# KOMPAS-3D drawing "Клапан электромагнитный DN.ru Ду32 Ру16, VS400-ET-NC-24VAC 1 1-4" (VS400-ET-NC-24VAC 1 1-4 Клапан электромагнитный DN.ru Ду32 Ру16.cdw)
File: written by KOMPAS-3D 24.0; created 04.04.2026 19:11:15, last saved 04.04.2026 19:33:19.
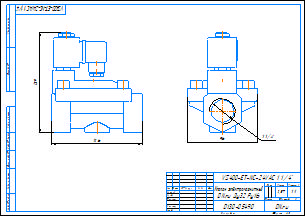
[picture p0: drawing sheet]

Document properties: c3d_UniqueCompID: ef56311e-7521-43dc-8291-0e6108b3d81d; Обозначение: VS400-ET-NC-220VAC 1; Наименование: Клапан электромагнитный DN.ru Ду25 Ру16; Автор: artio; Класс точности: c; Знак неуказанной шероховатости: Шероховатость не задана; Рассекать на разрезах: Да; c3d_UniqueCompID: ef56311e-7521-43dc-8291-0e6108b3d81d; Обозначение: VS400-ET-NC-220VAC 1-2; Наименование: Клапан электромагнитный DN.ru Ду15 Ру16; Автор: artio; Класс точности: c; Знак неуказанной шероховатости: Шероховатость не задана; Рассекать на разрезах: Да; c3d_UniqueCompID: ef56311e-7521-43dc-8291-0e6108b3d81d; Обозначение: VS400-ET-NC-220VAC 3-4; Наименование: Клапан электромагнитный DN.ru Ду20 Ру16; Автор: artio; Класс точности: c; Знак неуказанной шероховатости: Шероховатость не задана; Рассекать на разрезах: Да; c3d_UniqueCompID: ef56311e-7521-43dc-8291-0e6108b3d81d; Обозначение: VS400-ET-NC-220VAC 1 1-4; Наименование: Клапан электромагнитный DN.ru Ду32 Ру16; Автор: artio; Класс точности: c; Знак неуказанной шероховатости: Шероховатость не задана; Рассекать на разрезах: Да; c3d_UniqueCompID: ef56311e-7521-43dc-8291-0e6108b3d81d; Обозначение: VS400-ET-NC-220VAC 3-8; Наименование: Клапан электромагнитный DN.ru Ду10 Ру16; Автор: artio; Класс точности: c; Знак неуказанной шероховатости: Шероховатость не задана; Рассекать на разрезах: Да; Автор: artio; Форматы листов документа: A3; Полное имя файла: VS400-ET-NC-24VAC 1 1-4 Клапан электромагнитный DN.ru Ду32 Ру16.m3d; Масса: 2.569; Наименование: Клапан электромагнитный DN.ru Ду32 Ру16; Количество листов документа: 1; Примечание: D130-05490

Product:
- Body: Тело 1  | qty 1
    Масса: 4.144257
- Part/product: Клапан электромагнитный DN.ru Ду32 Ру16  | designation VS400-ET-NC-24VAC 1 1-4
    Масса: 2.569
    Раздел спецификации: Прочие изделия
    Примечание: D130-05490
    additional columns: ef56311e-7521-43dc-8291-0e6108b3d81d; VS400-ET-NC-220VAC 1 1-4; artio; c; Шероховатость не задана; Да

Views: Вид 1, Спереди
Referenced files in C:\Users\artio\OneDrive\Рабочий стол\Клапан электромагнитный DN.ru\VS400-ET-NC\VS400-ET-NC-24VDC\: VS400-ET-NC-24VDC 3-8 Клапан электромагнитный DN.ru Ду10 Ру16.m3d
Referenced files in C:\Users\artio\OneDrive\Рабочий стол\Клапан электромагнитный DN.ru\VS400\VS400-ET-NC\VS400-ET-NC-24VAC\Ду32\: VS400-ET-NC-24VAC 1 1-4 Клапан электромагнитный DN.ru Ду32 Ру16.m3d
Referenced files in C:\Users\artio\OneDrive\Рабочий стол\Клапан электромагнитный DN.ru\VS400-ET-NC\: VS400-ET-NC-24VDC 3-8 Клапан электромагнитный DN.ru Ду10 Ру16.cdw
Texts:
  VS400-ET-NC-24VAC 1 1-4
  Клапан электромагнитный
  DN.ru Ду32 Ру16
  VS400-ET-NC-24VAC 1 1/4"
  VS400-ET-NC-24VAC 1 1/4"-
  Клапан электромагнитный DN.ru Ду32 Ру16
  VS400-ET-NC-24VAC 1 1-4 Клапан электромагнитный DN.ru Ду32 Ру16
Dimensions and other numbers on the sheet: 0; 3; 2; 4; 96; 1 1/4"; 1:1; 1; 2,57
